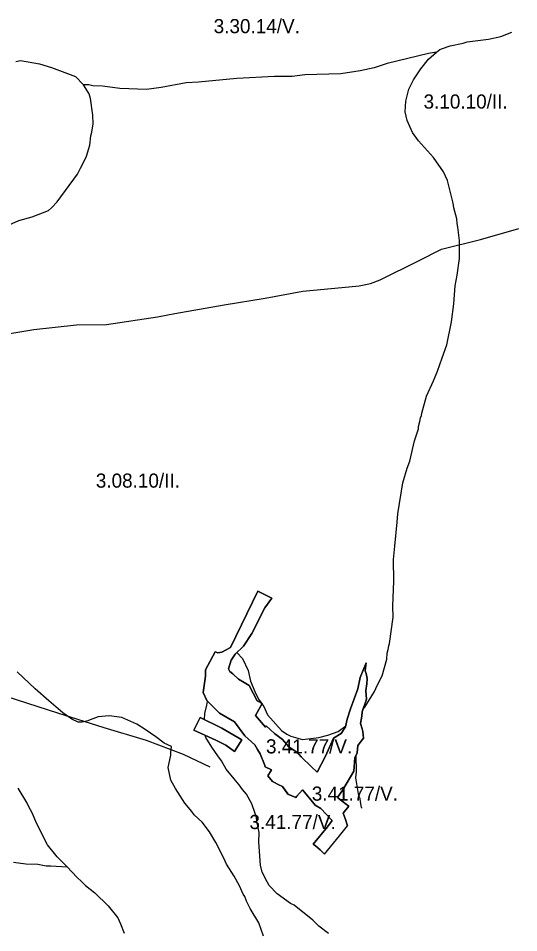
# Model space of a CAD drawing. Extents: x -555509 to -553014, y -1186753 to -1182560.
# Drawn here: x -553938 to -553231, y -1184262 to -1182970 of the extents above; entities that cross this region are included whole.
import ezdxf

# ---------------------------------------------------------------- set-up
doc = ezdxf.new("R2010")
doc.units = 0
for name, color, linetype in [('Level 29', 7, 'Continuous'), ('pěší_tr', 7, 'Continuous'), ('ZM2_KOO_legenda', 7, 'Continuous')]:
    doc.layers.add(name, color=color, linetype=linetype)

msp = doc.modelspace()

# ---------------------------------------------------------------- linework, layer by layer
at = {"layer": 'Level 29'}
for points in [[(-553346.7, -1183017.8), (-553342.2, -1183014), (-553339.7, -1183012.8), (-553327.4, -1183008.5), (-553309.1, -1183004.8), (-553303.6, -1183003), (-553273.1, -1182999.3), (-553255.8, -1182995.4), (-553240.5, -1182989.5)], [(-553346.7, -1183017.8), (-553358.3, -1183019.6), (-553416.4, -1183033.5), (-553435.1, -1183039.9), (-553454.6, -1183044.1), (-553482.1, -1183048.4), (-553533, -1183049.6), (-553550.8, -1183051.8), (-553575.8, -1183051.8), (-553629.2, -1183054.8), (-553683.1, -1183059.9), (-553700.5, -1183061.1), (-553736.1, -1183067.5), (-553756.9, -1183070.5), (-553794.2, -1183069.1), (-553818.8, -1183065.8), (-553832.8, -1183065.4), (-553838.2, -1183063.6), (-553845.9, -1183063.6)], [(-553450.9, -1183946.8), (-553448.2, -1183943.4), (-553434.6, -1183921.4), (-553430.8, -1183912.9), (-553423.6, -1183899.4), (-553417.2, -1183875.6), (-553416.4, -1183867.1), (-553415.1, -1183862), (-553414.3, -1183856.9), (-553413, -1183853.5), (-553407.9, -1183816.3), (-553408.4, -1183801), (-553407.1, -1183765.4), (-553407.5, -1183734.8), (-553405.8, -1183716.1), (-553402.4, -1183682.3), (-553401.6, -1183670.4), (-553394.4, -1183626.3), (-553388.4, -1183605.9), (-553384.6, -1183595.8), (-553377.8, -1183566.9), (-553372.3, -1183550), (-553372.3, -1183546.6), (-553370.2, -1183539.8), (-553369.4, -1183534.8), (-553368.1, -1183531.2), (-553367.6, -1183527.9), (-553360.9, -1183504.1), (-553351.1, -1183482.1), (-553345.6, -1183468.5), (-553338.8, -1183449.9), (-553332.4, -1183431.3), (-553325.7, -1183399), (-553322.3, -1183373.6), (-553320.6, -1183348.1), (-553317.6, -1183332.9), (-553314.2, -1183309.1), (-553314.2, -1183283.8), (-553316.4, -1183265), (-553317.6, -1183260), (-553318.1, -1183253.1), (-553322.3, -1183237.9), (-553323.1, -1183231.1), (-553331.2, -1183198.9), (-553336.7, -1183187), (-553351.1, -1183166.6), (-553372.3, -1183143), (-553380.8, -1183131.1), (-553388.4, -1183114.1), (-553391, -1183102.2), (-553390.1, -1183087), (-553385.9, -1183070), (-553382.5, -1183063.3), (-553379.1, -1183056.5), (-553368.9, -1183041.2), (-553358.3, -1183027.6), (-553346.7, -1183017.8)], [(-553941.3, -1183030.6), (-553934.9, -1183029.4), (-553908.2, -1183034), (-553891.2, -1183039.1), (-553856.9, -1183052.2), (-553845.9, -1183063.6)], [(-553964.2, -1183267.6), (-553937.1, -1183255.8), (-553918.4, -1183250.6), (-553895.5, -1183241.3), (-553890.8, -1183237.5), (-553883.2, -1183229), (-553854.4, -1183190), (-553850.1, -1183181.5), (-553848, -1183178.1), (-553841.6, -1183164.6), (-553837, -1183149.2), (-553835.3, -1183135.8), (-553834, -1183130.6), (-553832.3, -1183118.8), (-553832.8, -1183106.9), (-553836.1, -1183083.1), (-553837.8, -1183076.4), (-553845.9, -1183063.6)], [(-553504.9, -1184151.4), (-553511.3, -1184145.2), (-553517.9, -1184139.7), (-553520.9, -1184137.3), (-553500.7, -1184112.8), (-553494.1, -1184103.9), (-553496.2, -1184101.8), (-553502.7, -1184094.8), (-553510.1, -1184086.9), (-553518.3, -1184082.2), (-553526.5, -1184072.4), (-553536.4, -1184060.7), (-553544.1, -1184069.4), (-553545.6, -1184071.4), (-553556.8, -1184066.5), (-553564.7, -1184056), (-553570.4, -1184053), (-553576, -1184050), (-553578.8, -1184048.5), (-553585.2, -1184040.5), (-553580.1, -1184032.4), (-553589.1, -1184028.1), (-553590.1, -1184024.6), (-553596, -1184009.6), (-553599.8, -1184003.3), (-553603.6, -1183997), (-553617.9, -1183984.1), (-553632.2, -1183964.3), (-553653.4, -1183952), (-553671.5, -1183934.4), (-553676.7, -1183922.7), (-553673.2, -1183899.7), (-553673.4, -1183890.9), (-553659.7, -1183865.2), (-553656, -1183866.8), (-553650.2, -1183865.8), (-553638.1, -1183859.2), (-553599.3, -1183779.6), (-553579.5, -1183789.6), (-553589.5, -1183803.3), (-553607.6, -1183839.4), (-553619.4, -1183857.3), (-553631.4, -1183868.6), (-553636.9, -1183877.4), (-553640.7, -1183889.3), (-553638.9, -1183893.4), (-553634.7, -1183896.6), (-553626.7, -1183904.1), (-553618.7, -1183908.6), (-553611.6, -1183913.2), (-553606, -1183923.8), (-553600.5, -1183934.5), (-553593.3, -1183938.2), (-553602.6, -1183955.5), (-553588.6, -1183971.9), (-553587.4, -1183969.8), (-553581.8, -1183975.2), (-553576, -1183980.7), (-553564.7, -1183989.2), (-553555.7, -1183999.7), (-553545.2, -1184006.7), (-553541.4, -1184010.2), (-553537.9, -1184013.7), (-553523.5, -1184027.8), (-553515.4, -1184035.7), (-553503.5, -1184012.7), (-553498.1, -1184000.3), (-553492.3, -1183987.4), (-553481.7, -1183981), (-553475.4, -1183971.5), (-553473.1, -1183960.5), (-553468.3, -1183946.2), (-553458.1, -1183917.9), (-553454.6, -1183901.7), (-553446.1, -1183881.1), (-553447.5, -1183892.1), (-553446.4, -1183896), (-553444.8, -1183902.9), (-553445.2, -1183910.6), (-553446.7, -1183920.2), (-553446.7, -1183920.6), (-553445.8, -1183932.3), (-553452, -1183950.1), (-553452.1, -1183956.2), (-553454, -1183966.9), (-553452, -1183974.2), (-553450.9, -1183978.2), (-553450, -1183987.6), (-553458.2, -1183997.8), (-553458.7, -1184008.3), (-553462.3, -1184015.3), (-553463.7, -1184033.9), (-553463.7, -1184034.2), (-553479.4, -1184060.5), (-553486.7, -1184071.3), (-553478.4, -1184077.7), (-553476, -1184079.6), (-553470.9, -1184083.5), (-553478.8, -1184093.4), (-553476.1, -1184101.2), (-553472.5, -1184111.2)], [(-553628.9, -1183866.3), (-553621.2, -1183874.8), (-553613.1, -1183891.6), (-553609.8, -1183907), (-553603.4, -1183921.4), (-553598.3, -1183932.4), (-553594.6, -1183937.6)], [(-553591.5, -1184267.4), (-553597.9, -1184248.6), (-553610.2, -1184228.4), (-553615.2, -1184218.1), (-553617.8, -1184211.4), (-553619.9, -1184208), (-553625.4, -1184196.1), (-553632.6, -1184182.5), (-553643.7, -1184165.6), (-553647.5, -1184157.1), (-553658.9, -1184135), (-553667.8, -1184119.8), (-553678, -1184106.2), (-553689.4, -1184096), (-553692.8, -1184091), (-553702.6, -1184079.1), (-553715.8, -1184058.8), (-553722.1, -1184046.9), (-553725.9, -1184029), (-553722.1, -1184011.3), (-553722.1, -1184006.6), (-553721.4, -1184000), (-553721.2, -1183999), (-553731.9, -1183994.3), (-553743.7, -1183985.4), (-553758.6, -1183975.2), (-553770.4, -1183967.6), (-553791.6, -1183958.3), (-553809.4, -1183955.8), (-553825.1, -1183957.4), (-553836.6, -1183961.3), (-553839.6, -1183962.9), (-553847.6, -1183965), (-553853.5, -1183964.6), (-553862.4, -1183960.8), (-553874.8, -1183951.5), (-553894.6, -1183934.5), (-553914.1, -1183917.5), (-553939.6, -1183893.8)], [(-553674.8, -1183961.2), (-553674.2, -1183952.8), (-553671.6, -1183940.9), (-553670.6, -1183935.3)], [(-553593.7, -1183938.9), (-553591.1, -1183942.5), (-553585.6, -1183954.4), (-553566.1, -1183976.5), (-553558.4, -1183981.6), (-553552.9, -1183984.5), (-553536, -1183989.2), (-553513.1, -1183986.3), (-553500.4, -1183983.3), (-553485.9, -1183977.8), (-553475.1, -1183970.1)], [(-553689.7, -1183976.3), (-553681.1, -1183958.1), (-553650.1, -1183973.5), (-553621.8, -1183990), (-553632.4, -1184006.2), (-553644.5, -1183997.2), (-553658.7, -1183990.2), (-553689.7, -1183976.3)], [(-553499.5, -1184263.5), (-553513.1, -1184253.4), (-553521.6, -1184244.9), (-553548.2, -1184223.6), (-553553.4, -1184221.1), (-553572, -1184207.5), (-553583.4, -1184195.6), (-553586, -1184190.6), (-553593.2, -1184177), (-553595.8, -1184166.9), (-553597.9, -1184134.6), (-553597.4, -1184121), (-553600.4, -1184107.5), (-553601.7, -1184097.4), (-553602.9, -1184093.9), (-553607.6, -1184080.4), (-553615.2, -1184066.8), (-553621.2, -1184060), (-553625.9, -1184053.2), (-553632.6, -1184044.8), (-553644.1, -1184031.1), (-553650.9, -1184019.3), (-553655.9, -1184012.5), (-553664.2, -1184000), (-553672.9, -1183986.6), (-553674, -1183983.3)], [(-553454.1, -1184077.4), (-553454.6, -1184072.8), (-553456.7, -1184068.9), (-553460.9, -1184043.5), (-553460.1, -1184035), (-553460.4, -1184011.6)], [(-553868.8, -1184169.4), (-553882.8, -1184155), (-553896.8, -1184138), (-553912.4, -1184107.5), (-553918, -1184093.9), (-553923.5, -1184083.8), (-553926, -1184078.6), (-553938.3, -1184058.2)], [(-553452.9, -1184085.5), (-553454.1, -1184077.4)], [(-553452.9, -1184085.5), (-553452.6, -1184086.3)], [(-553944.7, -1184162.6), (-553927.3, -1184165.1), (-553910.3, -1184165.6), (-553898.5, -1184167.8), (-553892.1, -1184167.8), (-553868.8, -1184169.4)], [(-553868.8, -1184169.4), (-553855.2, -1184183.8), (-553848, -1184190.6), (-553842.9, -1184195.6), (-553829.8, -1184205.9), (-553810.7, -1184224.5), (-553797.1, -1184241.5), (-553793.3, -1184250), (-553788.2, -1184263.1)]]:
    msp.add_lwpolyline(points, dxfattribs=at)
at = {"layer": 'pěší_tr'}
for points in [[(-553955.5, -1183416.4), (-553916, -1183409.7), (-553855.5, -1183403), (-553813.3, -1183402.7), (-553741.2, -1183391.9), (-553716.7, -1183387.2), (-553646.8, -1183374.9), (-553589.2, -1183365.3), (-553535.7, -1183355.3), (-553480.4, -1183350.2), (-553456.2, -1183347.8), (-553440.2, -1183344.6), (-553426.3, -1183339.6), (-553372.4, -1183312.4), (-553339.6, -1183296), (-553284.5, -1183282.5), (-553230.6, -1183267.1)], [(-554122.5, -1183914.5), (-554115.1, -1183907.7), (-554109.8, -1183904.9), (-554045.2, -1183910.5), (-554003.6, -1183917.6), (-553954.2, -1183928.7), (-553882.6, -1183951.8), (-553817.2, -1183972.2), (-553757.4, -1183990.4), (-553704.9, -1184010.2), (-553667.2, -1184027.8)]]:
    msp.add_lwpolyline(points, dxfattribs=at)
at = {"layer": 'ZM2_KOO_legenda'}
for p, q in [((-553599.3, -1183779.6), (-553638.1, -1183859.2)), ((-553579.5, -1183789.6), (-553599.3, -1183779.6)), ((-553589.5, -1183803.3), (-553579.5, -1183789.6)), ((-553607.6, -1183839.4), (-553589.5, -1183803.3)), ((-553619.4, -1183857.3), (-553607.6, -1183839.4)), ((-553638.1, -1183859.2), (-553650.2, -1183865.8)), ((-553631.4, -1183868.6), (-553619.4, -1183857.3)), ((-553659.7, -1183865.2), (-553673.4, -1183890.9)), ((-553656, -1183866.8), (-553659.7, -1183865.2)), ((-553650.2, -1183865.8), (-553656, -1183866.8)), ((-553636.9, -1183877.4), (-553631.4, -1183868.6)), ((-553640.7, -1183889.3), (-553636.9, -1183877.4)), ((-553446.1, -1183881.1), (-553454.6, -1183901.7)), ((-553447.5, -1183892.1), (-553446.1, -1183881.1)), ((-553673.2, -1183899.7), (-553676.7, -1183922.7)), ((-553673.4, -1183890.9), (-553673.2, -1183899.7)), ((-553638.9, -1183893.4), (-553640.7, -1183889.3)), ((-553634.7, -1183896.6), (-553638.9, -1183893.4)), ((-553634, -1183897.1), (-553634.7, -1183896.6)), ((-553626.7, -1183904.1), (-553634, -1183897.1)), ((-553446.4, -1183896), (-553447.5, -1183892.1)), ((-553444.8, -1183902.9), (-553446.4, -1183896)), ((-553618.7, -1183908.6), (-553626.7, -1183904.1)), ((-553611.6, -1183913.2), (-553618.7, -1183908.6)), ((-553606, -1183923.8), (-553611.6, -1183913.2)), ((-553454.6, -1183901.7), (-553458.1, -1183917.9)), ((-553446.7, -1183920.2), (-553445.2, -1183910.6)), ((-553445.2, -1183910.6), (-553444.8, -1183902.9)), ((-553676.7, -1183922.7), (-553671.5, -1183934.4)), ((-553600.5, -1183934.5), (-553606, -1183923.8)), ((-553458.1, -1183917.9), (-553468.3, -1183946.2)), ((-553446.7, -1183920.6), (-553446.7, -1183920.2)), ((-553445.8, -1183932.3), (-553446.7, -1183920.6)), ((-553671.5, -1183934.4), (-553653.4, -1183952)), ((-553602.6, -1183955.5), (-553593.3, -1183938.2)), ((-553593.3, -1183938.2), (-553600.5, -1183934.5)), ((-553452, -1183950.1), (-553445.8, -1183932.3)), ((-553653.4, -1183952), (-553632.2, -1183964.3)), ((-553468.3, -1183946.2), (-553473.1, -1183960.5)), ((-553452.1, -1183956.2), (-553452, -1183950.1)), ((-553681.1, -1183958.1), (-553689.7, -1183976.3)), ((-553650.1, -1183973.5), (-553681.1, -1183958.1)), ((-553632.2, -1183964.3), (-553617.9, -1183984.1)), ((-553588.6, -1183971.9), (-553602.6, -1183955.5)), ((-553473.1, -1183960.5), (-553475.4, -1183971.5)), ((-553454, -1183966.9), (-553452.1, -1183956.2)), ((-553689.7, -1183976.3), (-553658.7, -1183990.2)), ((-553621.8, -1183990), (-553650.1, -1183973.5)), ((-553587.4, -1183969.8), (-553588.6, -1183971.9)), ((-553581.8, -1183975.2), (-553587.4, -1183969.8)), ((-553576, -1183980.7), (-553581.8, -1183975.2)), ((-553475.4, -1183971.5), (-553481.7, -1183981)), ((-553452, -1183974.2), (-553454, -1183966.9)), ((-553450.9, -1183978.2), (-553452, -1183974.2)), ((-553450, -1183987.6), (-553450.9, -1183978.2)), ((-553658.7, -1183990.2), (-553644.5, -1183997.2)), ((-553632.4, -1184006.2), (-553621.8, -1183990)), ((-553617.9, -1183984.1), (-553603.6, -1183997)), ((-553564.7, -1183989.2), (-553576, -1183980.7)), ((-553555.7, -1183999.7), (-553564.7, -1183989.2)), ((-553492.3, -1183987.4), (-553498.1, -1184000.3)), ((-553481.7, -1183981), (-553492.3, -1183987.4)), ((-553458.2, -1183997.8), (-553450, -1183987.6)), ((-553644.5, -1183997.2), (-553632.4, -1184006.2)), ((-553603.6, -1183997), (-553599.8, -1184003.3)), ((-553599.8, -1184003.3), (-553596, -1184009.6)), ((-553545.2, -1184006.7), (-553555.7, -1183999.7)), ((-553498.1, -1184000.3), (-553503.5, -1184012.7)), ((-553458.7, -1184008.3), (-553458.2, -1183997.8)), ((-553596, -1184009.6), (-553590.1, -1184024.6)), ((-553541.4, -1184010.2), (-553545.2, -1184006.7)), ((-553537.9, -1184013.7), (-553541.4, -1184010.2)), ((-553523.5, -1184027.8), (-553537.9, -1184013.7)), ((-553503.5, -1184012.7), (-553515.4, -1184035.7)), ((-553463.7, -1184033.9), (-553462.3, -1184015.3)), ((-553462.3, -1184015.3), (-553458.7, -1184008.3)), ((-553590.1, -1184024.6), (-553589.1, -1184028.1)), ((-553589.1, -1184028.1), (-553580.1, -1184032.4)), ((-553515.4, -1184035.7), (-553523.5, -1184027.8)), ((-553580.1, -1184032.4), (-553585.2, -1184040.5)), ((-553585.2, -1184040.5), (-553578.8, -1184048.5)), ((-553479.4, -1184060.5), (-553463.7, -1184034.2)), ((-553463.7, -1184034.2), (-553463.7, -1184033.9)), ((-553578.8, -1184048.5), (-553576, -1184050)), ((-553576, -1184050), (-553570.4, -1184053)), ((-553570.4, -1184053), (-553564.7, -1184056)), ((-553564.7, -1184056), (-553556.9, -1184066.3)), ((-553556.9, -1184066.3), (-553556.8, -1184066.5)), ((-553556.8, -1184066.5), (-553545.6, -1184071.4)), ((-553544.1, -1184069.4), (-553536.4, -1184060.7)), ((-553536.4, -1184060.7), (-553526.5, -1184072.4)), ((-553486.7, -1184071.3), (-553479.4, -1184060.5)), ((-553545.6, -1184071.4), (-553544.1, -1184069.4)), ((-553526.5, -1184072.4), (-553518.3, -1184082.2)), ((-553478.4, -1184077.7), (-553486.7, -1184071.3)), ((-553476, -1184079.6), (-553478.4, -1184077.7)), ((-553470.9, -1184083.5), (-553476, -1184079.6)), ((-553518.3, -1184082.2), (-553510.1, -1184086.9)), ((-553510.1, -1184086.9), (-553502.7, -1184094.8)), ((-553478.8, -1184093.4), (-553470.9, -1184083.5)), ((-553476.1, -1184101.2), (-553478.8, -1184093.4)), ((-553502.7, -1184094.8), (-553496.2, -1184101.8)), ((-553494.1, -1184103.9), (-553500.7, -1184112.8)), ((-553496.2, -1184101.8), (-553494.1, -1184103.9)), ((-553472.5, -1184111.2), (-553476.1, -1184101.2)), ((-553500.7, -1184112.8), (-553520.9, -1184137.3)), ((-553484.1, -1184125.6), (-553472.5, -1184111.2)), ((-553504.9, -1184151.4), (-553484.1, -1184125.6)), ((-553520.9, -1184137.3), (-553517.9, -1184139.7)), ((-553517.9, -1184139.7), (-553511.3, -1184145.2)), ((-553511.3, -1184145.2), (-553504.9, -1184151.4))]:
    msp.add_line(p, q, dxfattribs=at)

# ---------------------------------------------------------------- texts
at = {"layer": 'Level 29'}
for s, p in [('3.30.14/V.', (-553661.8, -1182990.8)), ('3.10.10/II.', (-553365.1, -1183097.4)), ('3.08.10/II.', (-553828.4, -1183633.3)), ('3.41.77/V.', (-553587.8, -1184009)), ('3.41.77/V.', (-553523.1, -1184075.8)), ('3.41.77/V.', (-553611.2, -1184115.9))]:
    msp.add_text(s, height=20, dxfattribs=at).set_placement(p)

doc.saveas('drawing.dxf')
